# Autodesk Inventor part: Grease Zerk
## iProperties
Author: QBZ
Shininess: 27.0
PropertySet Name: _Private Model Information
Created: 2001-03
Part Number: Grease Zerk
Document SubType Name: Modeling
Designer: QBZ
Description: 1/8 NPT ST Zerk
Material: Steel, Mild
Control State: 0
Master: False
Checked Out: False
PropertySet Name: Design Tracking Control
Density: 0.0
Volumn: 0.0
Area: 0.0
PropertySet Name: Model Information
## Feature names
1. straight nipple [Revolution]
2. straight nipple cut [Revolution]
3. body [Revolution]
4. ball [Revolution]
5. ball cut [Revolution]
6. angle nipple [Revolution]
7. angle nipple cut [Revolution]
